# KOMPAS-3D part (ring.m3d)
File: created 02.10.2016 09:52:18, last saved 02.10.2016 09:53:24.
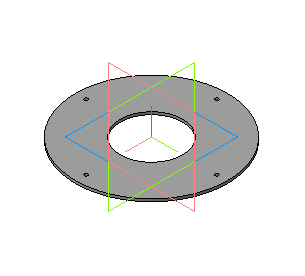
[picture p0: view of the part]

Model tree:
1. Эскиз:1
2. Операция выдавливания:1
     Расстояние 1 = 10; Расстояние 2 = 1.5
